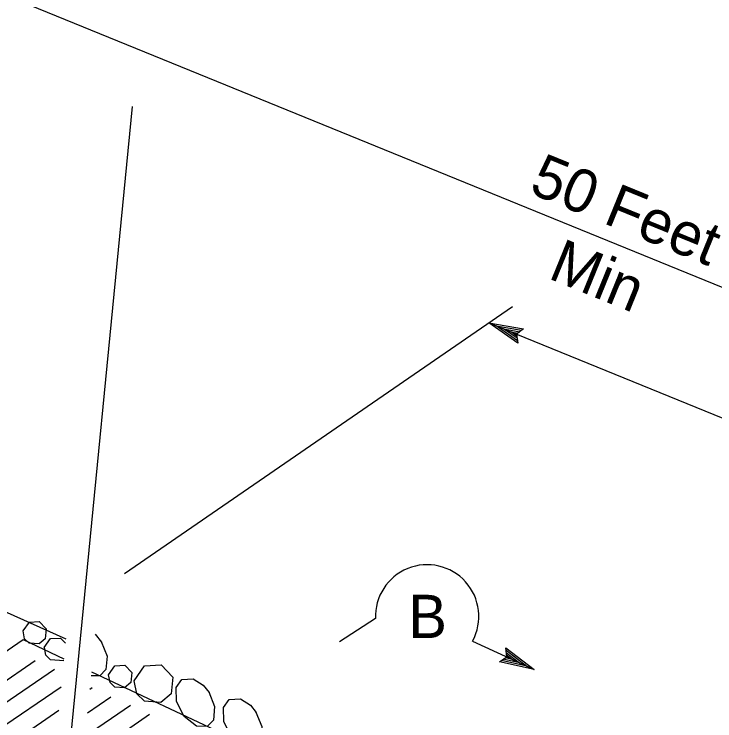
# Model space of a CAD drawing. Extents: x 6707406 to 6714471, y 1868570 to 1872341.
# Drawn here: x 6709921 to 6710037.9, y 1870319.2 to 1870437 of the extents above; entities that cross this region are included whole.
import ezdxf

# ---------------------------------------------------------------- set-up
doc = ezdxf.new("R2010")
doc.units = 0
for name, color, linetype in [('56 Stg 3 Anno', 7, 'Continuous'), ('57 Undefined', 7, 'Continuous'), ('60 Nongeo Data', 7, 'Continuous')]:
    doc.layers.add(name, color=color, linetype=linetype)

msp = doc.modelspace()

# ---------------------------------------------------------------- linework, layer by layer
at = {"layer": '56 Stg 3 Anno'}
for p, q in [((6709859.63, 1870464.61), (6710181.3, 1870333.54)), ((6709929.11, 1870303.2), (6709940.74, 1870421.63)), ((6709939.36, 1870343.76), (6710004.11, 1870388.26)), ((6710000.15, 1870385.54), (6710160.97, 1870320.01)), ((6710005, 1870382.18), (6710000.15, 1870385.54)), ((6710000.15, 1870385.54), (6710000.15, 1870385.54)), ((6710000.15, 1870385.54), (6710005.97, 1870384.55)), ((6710004.94, 1870382.57), (6710001.38, 1870385.04)), ((6710001.39, 1870385.04), (6710005.63, 1870384.32)), ((6710004.86, 1870382.98), (6710002.61, 1870384.54)), ((6710002.61, 1870384.54), (6710005.34, 1870384.07)), ((6710005.97, 1870384.55), (6710004.77, 1870383.66)), ((6710005.97, 1870384.55), (6710005.97, 1870384.55)), ((6710004.83, 1870383.35), (6710003.83, 1870384.04)), ((6710003.83, 1870384.04), (6710005.01, 1870383.84)), ((6710004.77, 1870383.66), (6710005, 1870382.18)), ((6710005, 1870382.18), (6710005, 1870382.18)), ((6709981.27, 1870336.23), (6709975.24, 1870332.35)), ((6709997.45, 1870332.49), (6710007.7, 1870327.76)), ((6710003.16, 1870329.85), (6710003, 1870331.35)), ((6710003, 1870331.35), (6710003, 1870331.35)), ((6710003, 1870331.35), (6710007.7, 1870327.76)), ((6710003.05, 1870330.95), (6710006.5, 1870328.32)), ((6710003.11, 1870330.54), (6710005.29, 1870328.88)), ((6710003.12, 1870330.17), (6710004.08, 1870329.43)), ((6710001.93, 1870329.02), (6710003.16, 1870329.85)), ((6710007.7, 1870327.76), (6710001.93, 1870329.02)), ((6710001.93, 1870329.02), (6710001.93, 1870329.02)), ((6710006.48, 1870328.32), (6710002.28, 1870329.23)), ((6710005.29, 1870328.88), (6710002.57, 1870329.47)), ((6710004.08, 1870329.43), (6710002.92, 1870329.68)), ((6710007.7, 1870327.76), (6710007.7, 1870327.76))]:
    msp.add_line(p, q, dxfattribs=at)
msp.add_arc((6709989.87, 1870336.6), 8.62, 331.4936, 182.464, dxfattribs=at)
at = {"layer": '60 Nongeo Data'}
for p, q in [((6709846.99, 1870369.89), (6709929.61, 1870332.83)), ((6709845.05, 1870279.98), (6709922.46, 1870332.74)), ((6709922.46, 1870332.74), (6709929.28, 1870329.53)), ((6709851.95, 1870279.8), (6709924.47, 1870329.23)), ((6709855.14, 1870278.31), (6709927.7, 1870327.77)), ((6709933.89, 1870327.37), (6709972.77, 1870309.11)), ((6709858.32, 1870276.81), (6709928.82, 1870324.87)), ((6709933.61, 1870324.47), (6709934.01, 1870324.74)), ((6709933.22, 1870320.54), (6709937.12, 1870323.2)), ((6709861.5, 1870275.32), (6709928.44, 1870320.94)), ((6709932.84, 1870316.62), (6709940.39, 1870321.77)), ((6709932.45, 1870312.69), (6709943.58, 1870320.28))]:
    msp.add_line(p, q, dxfattribs=at)
for points in [[(6709922.46, 1870334.17), (6709923.51, 1870335.66), (6709925.17, 1870335.75), (6709926.33, 1870334.55), (6709926.16, 1870332.87), (6709925.13, 1870332.01), (6709923.49, 1870332.13), (6709922.71, 1870332.88), (6709922.46, 1870334.17)], [(6709934.51, 1870333.65), (6709935.57, 1870332.32)], [(6709926, 1870331.41), (6709927.05, 1870332.89), (6709928.71, 1870332.99), (6709929.54, 1870332.13)], [(6709935.51, 1870332.42), (6709936.48, 1870329.98), (6709936.28, 1870327.74), (6709935.27, 1870326.67), (6709933.83, 1870326.7)], [(6709929.25, 1870329.2), (6709927.03, 1870329.36), (6709926.26, 1870330.12), (6709926.01, 1870331.41)], [(6709936.74, 1870326.87), (6709937.78, 1870328.35), (6709939.45, 1870328.45), (6709940.61, 1870327.24), (6709940.44, 1870325.56), (6709939.41, 1870324.71), (6709937.77, 1870324.82), (6709936.99, 1870325.58), (6709936.74, 1870326.87)], [(6709941, 1870325.86), (6709942.74, 1870328.34), (6709945.52, 1870328.5), (6709947.45, 1870326.49), (6709947.17, 1870323.69), (6709945.45, 1870322.26), (6709942.71, 1870322.46), (6709941.42, 1870323.71), (6709941, 1870325.86)], [(6709953.44, 1870324), (6709954.41, 1870321.56), (6709954.21, 1870319.32), (6709953.2, 1870318.26), (6709951.38, 1870318.29), (6709949.31, 1870319.91), (6709948.07, 1870322.41), (6709948.02, 1870324.76), (6709948.97, 1870326.09), (6709950.84, 1870326.21), (6709952.52, 1870325.14), (6709953.5, 1870323.91)], [(6709961.31, 1870320.65), (6709962.27, 1870318.21), (6709962.08, 1870315.97), (6709961.07, 1870314.91), (6709959.25, 1870314.94), (6709957.18, 1870316.56), (6709955.93, 1870319.06), (6709955.89, 1870321.41), (6709956.83, 1870322.74), (6709958.71, 1870322.86), (6709960.39, 1870321.79), (6709961.37, 1870320.56)]]:
    msp.add_lwpolyline(points, dxfattribs=at)

# ---------------------------------------------------------------- texts
at = {"layer": '57 Undefined'}
for s, p in [('50 Feet', (6710006.64, 1870407.3)), ('Min', (6710009.84, 1870393.04))]:
    msp.add_text(s, height=7.2, rotation=337.8294, dxfattribs=at).set_placement(p)
msp.add_text('B', height=7.21, dxfattribs=at).set_placement((6709986.74, 1870332.99))

doc.saveas('drawing.dxf')
